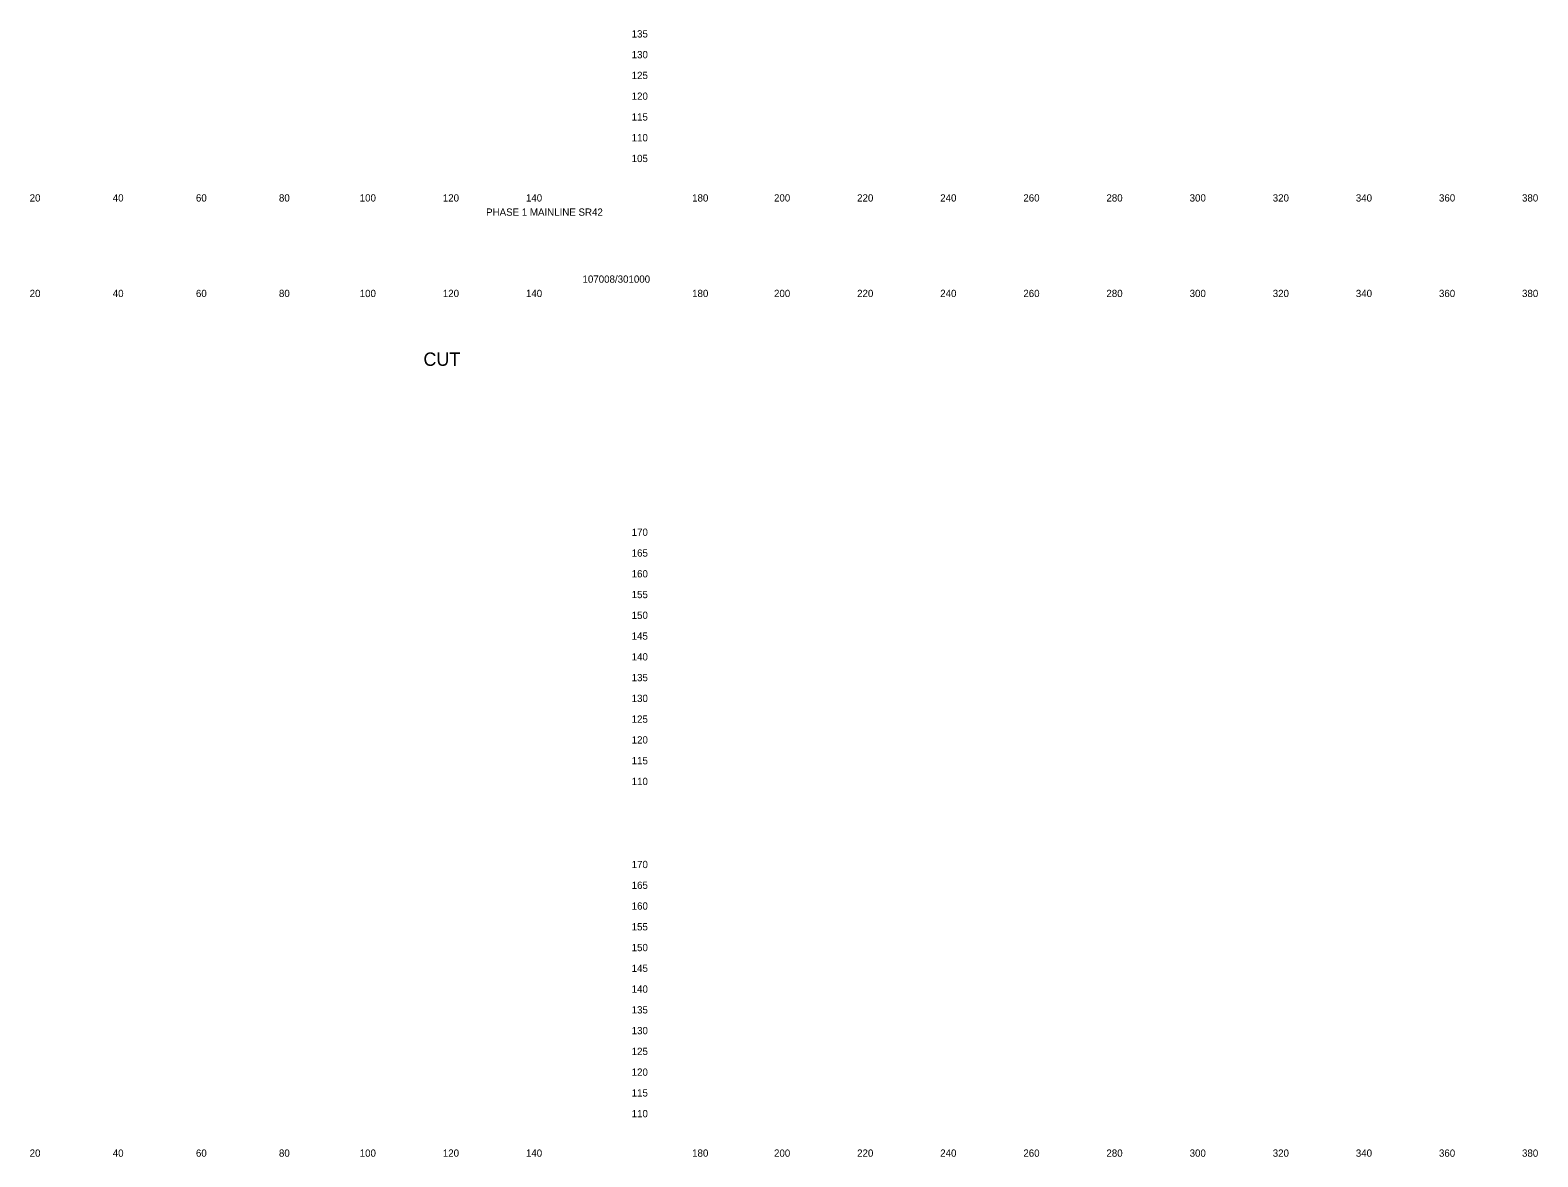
# Model space of a CAD drawing. Extents: x 21281 to 22024, y 6472 to 15198.
# Drawn here: x 21661.4 to 22024.2, y 9465.3 to 9736.6 of the extents above; entities that cross this region are included whole.
import ezdxf

# ---------------------------------------------------------------- set-up
doc = ezdxf.new("R2010")
doc.units = 0
doc.layers.add('XS_SHEET_LABELS_ELEVATION', color=7, linetype='Continuous')
doc.layers.add('XS_SHEET_LABELS_OFFSET', color=7, linetype='Continuous')

msp = doc.modelspace()

# ---------------------------------------------------------------- texts
at = {"layer": 'XS_SHEET_LABELS_ELEVATION'}
for s, p in [('  135  ', (21804.84, 9734.84)), ('  130  ', (21804.84, 9729.84)), ('  125  ', (21804.84, 9724.84)), ('  120  ', (21804.84, 9719.84)), ('  115  ', (21804.84, 9714.84)), ('  110  ', (21804.84, 9709.84)), ('  105  ', (21804.84, 9704.84)), ('  170  ', (21804.84, 9614.84)), ('  165  ', (21804.84, 9609.84)), ('  160  ', (21804.84, 9604.84)), ('  155  ', (21804.84, 9599.84)), ('  150  ', (21804.84, 9594.84)), ('  145  ', (21804.84, 9589.84)), ('  140  ', (21804.84, 9584.84)), ('  135  ', (21804.84, 9579.84)), ('  130  ', (21804.84, 9574.84)), ('  125  ', (21804.84, 9569.84)), ('  120  ', (21804.84, 9564.84)), ('  115  ', (21804.84, 9559.84)), ('  110  ', (21804.84, 9554.84)), ('  170  ', (21804.84, 9534.84)), ('  165  ', (21804.84, 9529.84)), ('  160  ', (21804.84, 9524.84)), ('  155  ', (21804.84, 9519.84)), ('  150  ', (21804.84, 9514.84)), ('  145  ', (21804.84, 9509.84)), ('  140  ', (21804.84, 9504.84)), ('  135  ', (21804.84, 9499.84)), ('  130  ', (21804.84, 9494.84)), ('  125  ', (21804.84, 9489.84)), ('  120  ', (21804.84, 9484.84)), ('  115  ', (21804.84, 9479.84)), ('  110  ', (21804.84, 9474.84))]:
    msp.add_text(s, height=1.75, dxfattribs=at).set_placement(p)
at = {"layer": 'XS_SHEET_LABELS_OFFSET'}
for s, height, p in [('  20  ', 1.75, (21659.95, 9695.34)), ('  40  ', 1.75, (21679.95, 9695.34)), ('  60  ', 1.75, (21699.97, 9695.34)), ('  80  ', 1.75, (21719.95, 9695.34)), ('  100  ', 1.75, (21739.39, 9695.34)), ('  120  ', 1.75, (21759.39, 9695.34)), ('  140  ', 1.75, (21779.39, 9695.34)), ('  180  ', 1.75, (21819.39, 9695.34)), ('  200  ', 1.75, (21839.1, 9695.34)), ('  220  ', 1.75, (21859.1, 9695.34)), ('  240  ', 1.75, (21879.1, 9695.34)), ('  260  ', 1.75, (21899.11, 9695.34)), ('  280  ', 1.75, (21919.1, 9695.34)), ('  300  ', 1.75, (21939.13, 9695.34)), ('  320  ', 1.75, (21959.13, 9695.34)), ('  340  ', 1.75, (21979.13, 9695.34)), ('  360  ', 1.75, (21999.14, 9695.34)), ('  380  ', 1.75, (22019.13, 9695.34)), ('PHASE 1 MAINLINE SR42', 1.75, (21771.11, 9691.92)), ('  20  ', 1.75, (21659.95, 9672.34)), ('  40  ', 1.75, (21679.95, 9672.34)), ('  60  ', 1.75, (21699.97, 9672.34)), ('  80  ', 1.75, (21719.95, 9672.34)), ('  100  ', 1.75, (21739.39, 9672.34)), ('  120  ', 1.75, (21759.39, 9672.34)), ('  140  ', 1.75, (21779.39, 9672.34)), ('107008/301000', 1.75, (21794.31, 9675.79)), ('  180  ', 1.75, (21819.39, 9672.34)), ('  200  ', 1.75, (21839.1, 9672.34)), ('  220  ', 1.75, (21859.1, 9672.34)), ('  240  ', 1.75, (21879.1, 9672.34)), ('  260  ', 1.75, (21899.11, 9672.34)), ('  280  ', 1.75, (21919.1, 9672.34)), ('  300  ', 1.75, (21939.13, 9672.34)), ('  320  ', 1.75, (21959.13, 9672.34)), ('  340  ', 1.75, (21979.13, 9672.34)), ('  360  ', 1.75, (21999.14, 9672.34)), ('  380  ', 1.75, (22019.13, 9672.34)), ('CUT', 3.222, (21756.03, 9655.78)), ('  20  ', 1.75, (21659.95, 9465.34)), ('  40  ', 1.75, (21679.95, 9465.34)), ('  60  ', 1.75, (21699.97, 9465.34)), ('  80  ', 1.75, (21719.95, 9465.34)), ('  100  ', 1.75, (21739.39, 9465.34)), ('  120  ', 1.75, (21759.39, 9465.34)), ('  140  ', 1.75, (21779.39, 9465.34)), ('  180  ', 1.75, (21819.39, 9465.34)), ('  200  ', 1.75, (21839.1, 9465.34)), ('  220  ', 1.75, (21859.1, 9465.34)), ('  240  ', 1.75, (21879.1, 9465.34)), ('  260  ', 1.75, (21899.11, 9465.34)), ('  280  ', 1.75, (21919.1, 9465.34)), ('  300  ', 1.75, (21939.13, 9465.34)), ('  320  ', 1.75, (21959.13, 9465.34)), ('  340  ', 1.75, (21979.13, 9465.34)), ('  360  ', 1.75, (21999.14, 9465.34)), ('  380  ', 1.75, (22019.13, 9465.34))]:
    msp.add_text(s, height=height, dxfattribs=at).set_placement(p)

doc.saveas('drawing.dxf')
